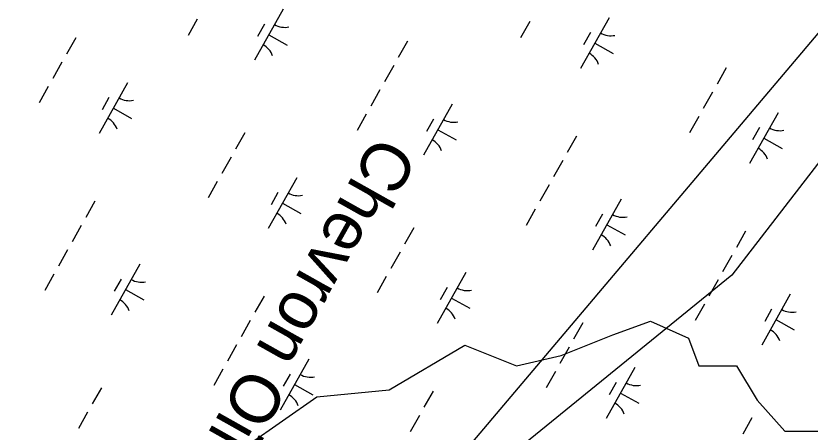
# Model space of a CAD drawing. Extents: x 3913936 to 3933962, y 195330 to 217741.
# Drawn here: x 3921642 to 3922323, y 202128 to 202485 of the extents above; entities that cross this region are included whole.
import ezdxf

# ---------------------------------------------------------------- set-up
doc = ezdxf.new("R2010")
doc.units = 0
for name, color, linetype in [('V-BLDG-IDEN', 7, 'Continuous'), ('V-RIVR-EDGE', 7, 'Continuous'), ('V-UTIL-LINE', 7, 'Continuous'), ('V-WETL-SWMP', 7, 'Continuous')]:
    doc.layers.add(name, color=color, linetype=linetype)

msp = doc.modelspace()

# ---------------------------------------------------------------- linework, layer by layer
at = {"layer": 'V-RIVR-EDGE'}
msp.add_lwpolyline([(3921637.55, 202069.82), (3921684.75, 202075.72), (3921714.25, 202069.82), (3921764.41, 202052.12), (3921808.66, 202055.07), (3921841.12, 202117.02), (3921900.12, 202158.33), (3921962.08, 202164.23), (3922026.98, 202202.58), (3922071.24, 202184.88), (3922109.59, 202193.73), (3922153.85, 202211.43), (3922186.3, 202223.24), (3922218.75, 202208.48), (3922227.6, 202184.88), (3922260.06, 202184.88), (3922277.76, 202155.38), (3922301.36, 202128.83), (3922342.66, 202128.83)], dxfattribs=at)
at = {"layer": 'V-UTIL-LINE'}
for points in [[(3928315.82, 212388.13), (3926944.7, 210748.94), (3926592.74, 210251.47), (3926408.93, 209914.99), (3925628.64, 208474.44), (3925139.98, 207727.42), (3924555.96, 206253.65), (3924055.82, 204771.45), (3923484.9, 203858.52), (3922256.01, 202262.65), (3921816.4, 201905.57), (3920704.84, 200345.08), (3920462.44, 200062.72)], [(3928328.32, 212380.93), (3926784.14, 210502.92), (3926424.72, 209908.68), (3925640.45, 208467.64), (3924952.2, 207329.25), (3923971.74, 204752.16), (3923252.9, 203563.68), (3921560.17, 201558.84), (3920397.87, 200112.86)]]:
    msp.add_lwpolyline(points, dxfattribs=at)
at = {"layer": 'V-WETL-SWMP'}
for p, q in [((3921871.08, 202490.82), (3921846.58, 202447.23)), ((3922150.69, 202483.6), (3922126.18, 202440.01)), ((3921797.4, 202482.25), (3921789.56, 202468.3)), ((3921855.05, 202478.03), (3921849.17, 202467.57)), ((3922082.59, 202480.24), (3922074.75, 202466.29)), ((3921858.83, 202469.02), (3921874.52, 202460.2)), ((3922134.65, 202470.81), (3922128.77, 202460.35)), ((3921693.14, 202466.34), (3921685.3, 202452.39)), ((3921977.68, 202463.5), (3921969.84, 202449.55)), ((3922138.44, 202461.8), (3922154.13, 202452.98)), ((3921681.38, 202445.42), (3921673.54, 202431.47)), ((3921965.92, 202442.58), (3921958.08, 202428.63)), ((3922251.11, 202440.57), (3922243.27, 202426.62)), ((3921669.62, 202424.5), (3921661.78, 202410.55)), ((3921737.72, 202427.86), (3921713.22, 202384.27)), ((3921954.16, 202421.66), (3921946.31, 202407.71)), ((3921721.68, 202415.07), (3921715.8, 202404.61)), ((3922239.35, 202419.65), (3922231.51, 202405.7)), ((3922016.08, 202409.31), (3921991.58, 202365.72)), ((3921725.47, 202406.06), (3921741.16, 202397.24)), ((3921942.39, 202400.74), (3921934.55, 202386.79)), ((3922295.68, 202402.09), (3922271.18, 202358.5)), ((3922000.05, 202396.52), (3921994.17, 202386.06)), ((3922227.59, 202398.73), (3922219.75, 202384.78)), ((3922003.83, 202387.51), (3922019.52, 202378.69)), ((3922279.65, 202389.31), (3922273.77, 202378.85)), ((3921838.14, 202384.83), (3921830.3, 202370.88)), ((3922122.67, 202381.99), (3922114.83, 202368.04)), ((3922283.43, 202380.29), (3922299.12, 202371.47)), ((3921826.38, 202363.91), (3921818.54, 202349.96)), ((3922110.91, 202361.07), (3922103.07, 202347.12)), ((3921882.71, 202346.35), (3921858.21, 202302.76)), ((3921814.62, 202342.99), (3921806.78, 202329.04)), ((3922099.15, 202340.15), (3922091.31, 202326.2)), ((3921866.68, 202333.57), (3921860.8, 202323.1)), ((3921709.71, 202326.25), (3921701.86, 202312.3)), ((3922161.08, 202327.8), (3922136.58, 202284.21)), ((3921870.46, 202324.55), (3921886.15, 202315.73)), ((3922087.39, 202319.23), (3922079.55, 202305.28)), ((3922145.04, 202315.02), (3922139.16, 202304.56)), ((3921697.94, 202305.33), (3921690.1, 202291.38)), ((3922148.83, 202306), (3922164.52, 202297.18)), ((3921983.14, 202303.32), (3921975.3, 202289.37)), ((3922267.67, 202300.48), (3922259.83, 202286.54)), ((3921686.18, 202284.41), (3921678.34, 202270.46)), ((3921971.38, 202282.4), (3921963.54, 202268.45)), ((3922255.91, 202279.56), (3922248.07, 202265.61)), ((3921748.11, 202272.06), (3921723.61, 202228.47)), ((3922027.71, 202264.84), (3922003.21, 202221.25)), ((3921674.42, 202263.49), (3921666.58, 202249.54)), ((3921732.08, 202259.28), (3921726.19, 202248.81)), ((3921959.61, 202261.48), (3921951.77, 202247.53)), ((3922244.15, 202258.64), (3922236.31, 202244.69)), ((3922011.68, 202252.06), (3922005.8, 202241.6)), ((3921735.86, 202250.26), (3921751.55, 202241.44)), ((3921854.7, 202244.74), (3921846.86, 202230.79)), ((3922306.08, 202246.29), (3922281.58, 202202.7)), ((3922015.46, 202243.04), (3922031.15, 202234.22)), ((3922232.39, 202237.72), (3922224.55, 202223.77)), ((3922290.04, 202233.51), (3922284.16, 202223.05)), ((3921842.94, 202223.82), (3921835.1, 202209.87)), ((3922293.83, 202224.5), (3922309.52, 202215.67)), ((3922128.13, 202221.81), (3922120.29, 202207.87)), ((3921831.18, 202202.9), (3921823.34, 202188.95)), ((3922116.37, 202200.89), (3922108.53, 202186.94)), ((3921893.11, 202190.55), (3921868.61, 202146.96)), ((3922172.71, 202183.33), (3922148.21, 202139.74)), ((3921819.42, 202181.98), (3921811.58, 202168.03)), ((3921877.07, 202177.77), (3921871.19, 202167.31)), ((3922104.61, 202179.97), (3922096.77, 202166.02)), ((3922156.67, 202170.55), (3922150.79, 202160.09)), ((3921715.16, 202166.07), (3921707.32, 202152.13)), ((3921880.86, 202168.75), (3921896.55, 202159.93)), ((3921999.7, 202163.23), (3921991.86, 202149.29)), ((3922160.46, 202161.54), (3922176.15, 202152.72)), ((3921703.4, 202145.15), (3921695.56, 202131.2)), ((3921987.94, 202142.31), (3921980.1, 202128.36)), ((3922273.13, 202140.3), (3922265.29, 202126.36))]:
    msp.add_line(p, q, dxfattribs=at)
for centre, start, end in [((3921872.58, 202492.98), 239.88608, 281.42974), ((3922152.18, 202485.77), 239.88608, 281.42974), ((3921845.51, 202444.83), 19.88608, 61.42973), ((3922125.11, 202437.61), 19.88608, 61.42973), ((3921739.21, 202430.02), 239.88608, 281.42974), ((3921712.14, 202381.87), 19.88608, 61.42973), ((3922017.57, 202411.48), 239.88608, 281.42974), ((3922297.18, 202404.26), 239.88608, 281.42974), ((3921990.5, 202363.32), 19.88608, 61.42973), ((3922270.1, 202356.1), 19.88608, 61.42973), ((3921884.21, 202348.52), 239.88608, 281.42974), ((3921857.14, 202300.36), 19.88608, 61.42973), ((3922162.57, 202329.97), 239.88608, 281.42974), ((3922135.5, 202281.81), 19.88608, 61.42973), ((3921749.6, 202274.23), 239.88608, 281.42974), ((3922029.2, 202267.01), 239.88608, 281.42974), ((3921722.53, 202226.07), 19.88608, 61.42973), ((3922002.13, 202218.85), 19.88608, 61.42973), ((3922307.57, 202248.46), 239.88608, 281.42974), ((3922280.5, 202200.3), 19.88608, 61.42973), ((3921894.6, 202192.72), 239.88608, 281.42974), ((3922174.2, 202185.5), 239.88608, 281.42974), ((3921867.53, 202144.56), 19.88608, 61.42973), ((3922147.13, 202137.34), 19.88608, 61.42973)]:
    msp.add_arc(centre, 17.62, start, end, dxfattribs=at)

# ---------------------------------------------------------------- texts
at = {"layer": 'V-BLDG-IDEN'}
msp.add_text('Chevron Oil Co.', height=41.9999, rotation=240.65788, dxfattribs=at).set_placement((3921951, 202384.58))

doc.saveas('drawing.dxf')
